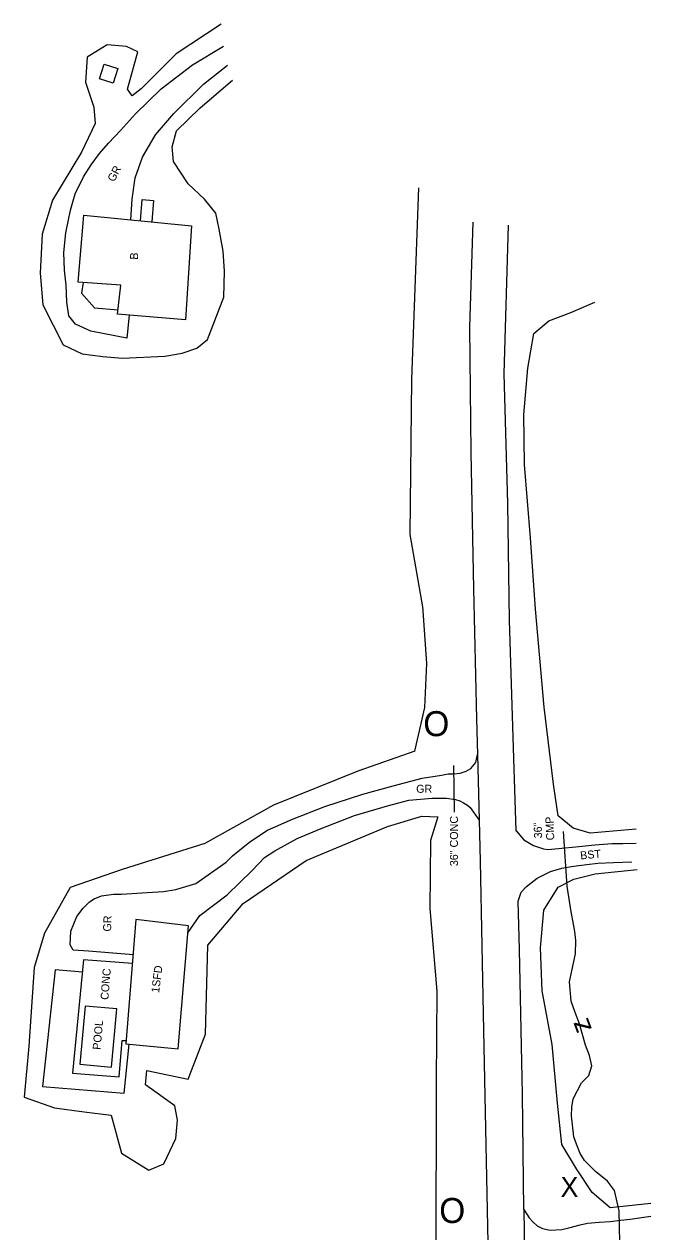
# Model space of a CAD drawing. Extents: x 2030130 to 2036320, y 723205 to 762423.
# Drawn here: x 2032288 to 2032602, y 749995 to 750598 of the extents above; entities that cross this region are included whole.
import ezdxf

# ---------------------------------------------------------------- set-up
doc = ezdxf.new("R2010")
doc.units = 0
for name, color, linetype in [('Draft_Station Cardinal Points', 7, 'Continuous'), ('Draft_Station Labels Major', 7, 'Continuous'), ('Draft_Station Tics Major', 7, 'Continuous'), ('Draft_Station Tics Minor', 7, 'Continuous'), ('Exist Terrain Model Ground Surface', 7, 'Continuous'), ('Old_Level_23', 7, 'Continuous'), ('Old_Level_26', 7, 'Continuous'), ('Old_Level_28', 7, 'Continuous'), ('Prop Alignment Horizontal', 7, 'Continuous'), ('Prop Alignment Vertical', 7, 'Continuous')]:
    doc.layers.add(name, color=color, linetype=linetype)

msp = doc.modelspace()

# ---------------------------------------------------------------- linework, layer by layer
at = {"layer": 'Draft_Station Labels Major'}
for points in [[(2032340.9, 750452.58), (2032339.82, 750441.05), (2032321.8, 750444.56), (2032314.01, 750448.12), (2032310.77, 750452.23), (2032309.8, 750459.07), (2032309.38, 750467.57), (2032308.6, 750475.1), (2032308.18, 750483.98), (2032309.3, 750493.76), (2032311.55, 750505), (2032313.85, 750513.25), (2032318.17, 750521.72), (2032321.95, 750527.67), (2032326.12, 750533.44), (2032330.58, 750538.62), (2032336.58, 750544.8), (2032344.1, 750553.12), (2032356.87, 750565.68), (2032372.54, 750577.69), (2032388.11, 750587.06)], [(2032341.75, 750500.21), (2032342.49, 750510.57), (2032343.88, 750521.23), (2032347.6, 750531.52), (2032354.01, 750542.73), (2032363.23, 750553.4), (2032378.1, 750568.01), (2032390.14, 750577.55)], [(2032512.76, 750499.1), (2032511, 750446.68), (2032511.71, 750384.01), (2032513.08, 750315.91), (2032514.6, 750250.93), (2032515.06, 750233.01)], [(2032534.31, 750194.98), (2032533.4, 750225.97), (2032530.97, 750300.06), (2032530.13, 750358.46), (2032528.41, 750423.25), (2032530.44, 750497.61)], [(2032392.57, 750182.48), (2032401.27, 750189.48), (2032410.09, 750195.31), (2032422.5, 750200.81), (2032438.66, 750207.15), (2032457.73, 750213.32), (2032472.87, 750217.41), (2032487.43, 750221.2), (2032496.98, 750222.79), (2032500.36, 750223.33), (2032503.17, 750223.46), (2032506.36, 750223.8), (2032509.44, 750224.72), (2032511.65, 750226.01), (2032514.22, 750229.04), (2032515.06, 750233.01)], [(2032515.06, 750233.01), (2032515.89, 750200.22)], [(2032370.26, 750144.03), (2032376.29, 750152.62), (2032389.98, 750162.97), (2032402.38, 750175.15), (2032408.48, 750181.53), (2032413.76, 750184.9), (2032424.89, 750191.16), (2032436.82, 750196.07), (2032453.47, 750202.6), (2032470.04, 750207.49), (2032480.74, 750210.25), (2032492.44, 750211.29), (2032499.6, 750211.2), (2032503.96, 750210.59), (2032506.2, 750209.95), (2032507.95, 750209), (2032510.1, 750207.68), (2032511.28, 750206.53), (2032515.89, 750200.22)], [(2032515.89, 750200.22), (2032516.41, 750179.73), (2032518.02, 750095.15), (2032520.14, 749989.03), (2032523.59, 749884.29), (2032524.93, 749791.93)], [(2032534.31, 750194.98), (2032538.15, 750190.49), (2032543.03, 750187.66), (2032547.99, 750185.89), (2032550.22, 750185.63), (2032555.54, 750186.1), (2032565.69, 750187.02), (2032573.71, 750188), (2032582.41, 750188.61), (2032587.73, 750188.59), (2032594.31, 750188.69)], [(2032534.32, 750194.77), (2032534.31, 750194.98)], [(2032342.85, 750132.92), (2032320.58, 750134.78), (2032312.93, 750135.35), (2032311.44, 750137.94), (2032311.83, 750144.81), (2032314.72, 750152.11), (2032317.95, 750156.32), (2032321.1, 750159.37), (2032323.4, 750160.95), (2032327.15, 750162.45), (2032333.04, 750163.22), (2032337.01, 750163.27), (2032349.97, 750164.04), (2032358.09, 750164.64), (2032364.17, 750165.6), (2032374.19, 750168.65), (2032389.42, 750179.32), (2032392.57, 750182.48)], [(2032535.35, 750159.77), (2032536.93, 750164.25), (2032539.5, 750167.19), (2032544.77, 750171.33), (2032551.49, 750174.62), (2032557.18, 750176.35), (2032563.07, 750177.3), (2032569.73, 750178.17), (2032575.14, 750178.83), (2032583.07, 750179.14), (2032592.17, 750179.37)], [(2032538.17, 750005.66), (2032537.5, 750063.41), (2032536.07, 750135.58), (2032535.35, 750159.77)], [(2032538.17, 750005.66), (2032538.9, 749961.25)], [(2032538.17, 750005.66), (2032540.84, 750001.54), (2032542.61, 749999.53), (2032544.77, 749997.62), (2032547.5, 749996.21), (2032551.38, 749995.4), (2032554.19, 749995.54), (2032557.18, 749995.77), (2032560.75, 749996.5), (2032566.34, 749998.03), (2032570.01, 749998.86), (2032575.81, 749999.33), (2032581.42, 749999.8), (2032586.54, 750000.36), (2032591.37, 750000.91), (2032601.6, 750002.32)]]:
    msp.add_lwpolyline(points, dxfattribs=at)
at = {"layer": 'Draft_Station Tics Major'}
for points in [[(2032386.91, 750598.01), (2032364.48, 750583.17), (2032346.93, 750565.7), (2032342.34, 750562.15), (2032340.16, 750565.6), (2032345.31, 750584.25), (2032339.66, 750586.88), (2032329.98, 750587.7), (2032320, 750581.56), (2032319.02, 750568.97), (2032323.27, 750556.46), (2032323.97, 750548.34), (2032317.01, 750534.11), (2032302.65, 750510.11), (2032297.48, 750493), (2032296.41, 750473.64), (2032297.8, 750457.79), (2032307.96, 750437.82), (2032317.5, 750433.31), (2032327.78, 750431.91), (2032337.66, 750431.09), (2032358.73, 750432.17), (2032367.42, 750433.65), (2032374.74, 750436.07), (2032380.09, 750440.41), (2032388.3, 750461.62), (2032388.5, 750474.58), (2032387.97, 750484.64), (2032385.87, 750495.64), (2032384.21, 750503.55), (2032378.5, 750510.62), (2032370.45, 750518.25), (2032363.13, 750529.36), (2032362.45, 750536.71), (2032364.65, 750544.67), (2032376.48, 750556.26), (2032392.54, 750570.03)], [(2032485.61, 750516.23), (2032481.96, 750420.4), (2032481.15, 750342.99), (2032487.57, 750306.79)], [(2032594.36, 750195.7), (2032571.36, 750193.81), (2032562.82, 750196.21), (2032555.37, 750202.48), (2032553.01, 750218.32), (2032548.4, 750256.75), (2032544.01, 750305.64), (2032541.56, 750341.41), (2032538.52, 750377.93), (2032538.16, 750402.89), (2032540.14, 750426.14), (2032543.18, 750443.4), (2032550.64, 750449.7), (2032561.6, 750453.92), (2032573.72, 750459.13)], [(2032487.5, 750307.23), (2032489.58, 750278.59), (2032488.54, 750256.62), (2032483.49, 750234.8)], [(2032483.64, 750234.73), (2032455.19, 750224.78), (2032413.06, 750207.73), (2032378.7, 750188.65), (2032337.48, 750175.67), (2032311.49, 750166.59), (2032298.66, 750143.77), (2032293.49, 750126.66), (2032290.77, 750087.35), (2032288.42, 750061.82), (2032303.6, 750056.57), (2032318.34, 750054.46), (2032331.91, 750052.92), (2032337.02, 750033.84), (2032350.69, 750025.33), (2032358.19, 750028.53), (2032364.19, 750041.2), (2032365.03, 750050.3), (2032363.77, 750057.44), (2032349.1, 750068.07), (2032349.77, 750075.23), (2032370.34, 750070.89), (2032379.11, 750093.27), (2032380.21, 750137.79), (2032397.91, 750158.55), (2032429.33, 750180.1), (2032470.1, 750197.13), (2032487.25, 750202.22), (2032495.19, 750201.95), (2032491.52, 750190.16), (2032491.28, 750156.15), (2032494.7, 750114.87), (2032494.42, 750069.56), (2032494.19, 749980.78)], [(2032601.68, 750008.66), (2032581.35, 750006.59), (2032572.34, 750014.2), (2032564.43, 750026.08), (2032557.1, 750038.16), (2032555.06, 750058.84), (2032552.31, 750088.21), (2032547.28, 750115.03), (2032546.58, 750136.5), (2032548.24, 750155.29), (2032555.43, 750166.81), (2032563.11, 750170.79), (2032573.91, 750173.46), (2032594.85, 750175.58)]]:
    msp.add_lwpolyline(points, dxfattribs=at)
at = {"layer": 'Draft_Station Tics Minor'}
for p, q in [((2032503.5, 750204.26), (2032503.26, 750227.57)), ((2032559.79, 750167.24), (2032558.01, 750194.6)), ((2032586.28, 749981.38), (2032585.84, 750004.98))]:
    msp.add_line(p, q, dxfattribs=at)
at = {"layer": 'Exist Terrain Model Ground Surface'}
for points in [[(2032328.37, 750578.02), (2032335.17, 750575.9), (2032332.96, 750568.52), (2032326.06, 750570.74), (2032326.06, 750570.74)], [(2032318.27, 750502.5), (2032372.1, 750497.26), (2032369.09, 750450.25), (2032335.09, 750453.06), (2032336.82, 750467.64), (2032315.45, 750469.08)], [(2032344.31, 750150.66), (2032339.2, 750088.48), (2032365.43, 750085.95), (2032370.56, 750147.54)]]:
    msp.add_lwpolyline(points, close=True, dxfattribs=at)
for points in [[(2032346.54, 750499.74), (2032347.47, 750510.35), (2032353.09, 750509.95), (2032352.22, 750499.19)], [(2032317.92, 750468.91), (2032317.09, 750463.56), (2032323.58, 750456.3), (2032335.34, 750455.19)], [(2032342.5, 750128.67), (2032318.1, 750130.5), (2032312.63, 750073.91), (2032335.98, 750072.02), (2032337.46, 750090.24), (2032339.33, 750090.09)], [(2032317.51, 750124.38), (2032303.88, 750125.54), (2032297.66, 750067.19), (2032338.45, 750063.91), (2032340.94, 750088.32)]]:
    msp.add_lwpolyline(points, dxfattribs=at)
at = {"layer": 'Prop Alignment Horizontal'}
msp.add_lwpolyline([(2032585.84, 750004.98), (2032583.47, 750015.2), (2032580.01, 750019.89), (2032573.95, 750024.64), (2032568.54, 750030.18), (2032566.36, 750033.72), (2032564.46, 750038.34), (2032563.15, 750042.1), (2032562.03, 750052.53), (2032562.16, 750056.88), (2032562.78, 750061.05), (2032567.02, 750068.95), (2032570.64, 750072.68), (2032572.12, 750077.44), (2032570.98, 750082.65), (2032568.97, 750087.75), (2032567.54, 750093.15), (2032566.01, 750098.44), (2032563.8, 750104.22), (2032561.78, 750109.8), (2032560.96, 750119.56), (2032562.69, 750127.23), (2032564.05, 750133.54), (2032564.15, 750140.21), (2032563.7, 750144.66), (2032562.65, 750150.16), (2032561.91, 750154.4), (2032559.79, 750167.24)], dxfattribs=at)
msp.add_lwpolyline([(2032318.93, 750107.4), (2032316.25, 750078.26), (2032332, 750076.8), (2032334.68, 750105.95)], close=True, dxfattribs=at)

# ---------------------------------------------------------------- texts
at = {"layer": 'Draft_Station Cardinal Points'}
for p in [(2032487.94, 750242.23), (2032495.91, 749998.97)]:
    msp.add_text('O', height=12.5, dxfattribs=at).set_placement(p)
at = {"layer": 'Draft_Station Tics Major'}
msp.add_text('X', height=10, dxfattribs=at).set_placement((2032556.54, 750012.01))
at = {"layer": 'Old_Level_23'}
for s, rotation, p in [('GR', 62.11619, (2032333.37, 750518.86)), ('GR', 0.00002, (2032484.38, 750213.94)), ('BST', 5.26523, (2032566.54, 750180.62)), ('GR', 88.31647, (2032331.86, 750144.54))]:
    msp.add_text(s, height=4, rotation=rotation, dxfattribs=at).set_placement(p)
at = {"layer": 'Old_Level_26'}
for s, rotation, p in [('36" CONC', 90.00002, (2032505.26, 750177.28)), ('CMP', 92.36229, (2032553.41, 750190.25)), ('36"', 92.36229, (2032547.36, 750191.26))]:
    msp.add_text(s, height=4, rotation=rotation, dxfattribs=at).set_placement(p)
at = {"layer": 'Old_Level_28'}
for s, rotation, p in [('B', 86.16693, (2032345.25, 750480.21)), ('CONC', 85.48372, (2032330.52, 750110.36)), ('1SFD', 82.8076, (2032355.87, 750113.83))]:
    msp.add_text(s, height=4, rotation=rotation, dxfattribs=at).set_placement(p)
at = {"layer": 'Prop Alignment Horizontal'}
msp.add_text('z', height=10, rotation=110.68365, dxfattribs=at).set_placement((2032572.31, 750095.9))
at = {"layer": 'Prop Alignment Vertical'}
msp.add_text('POOL', height=4, rotation=84.91755, dxfattribs=at).set_placement((2032326.61, 750085.38))

doc.saveas('drawing.dxf')
